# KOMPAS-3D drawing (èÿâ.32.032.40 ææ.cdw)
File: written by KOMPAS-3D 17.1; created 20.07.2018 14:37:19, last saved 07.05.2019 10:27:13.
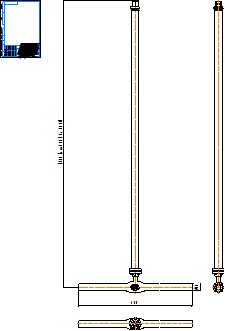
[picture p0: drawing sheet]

Sheet 1: A4, portrait

Title block, sheet 1: name: КШГ.32.032.40 СС; material: Внимание! Данный продукт является объектом авторского права ООО «Торговый Дом АДЛ». / Запрещается изменение, копирование, распространение / (в том числе путем копирования на другие сайты и ресурсы в Интернете) / или любое иное использование информации и объектов без предварительного / согласия правообладателя (ООО «Торговый Дом АДЛ»).; sheets: 1; organisation: ООО "Торговый дом АДЛ"; sheet format: A4; stored path: C:\Users\tra\Desktop\2д чертежи\Шаровые краны БИВАЛ\КШ_Бивал_серия_32\KOMPAS 2D\КШГ.32.032.40 СС.cdw

Views: Вид 1, Проекционный вид 2
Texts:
  kka
  adl
  (от 203,1 до 5000)
Dimensions and other numbers on the sheet: 600; 38; 1500; 1:1; 1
